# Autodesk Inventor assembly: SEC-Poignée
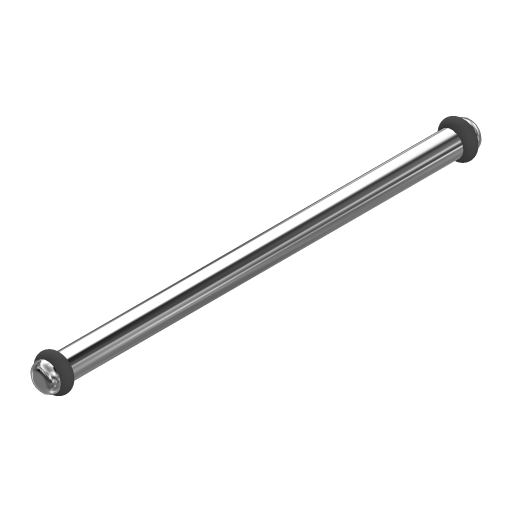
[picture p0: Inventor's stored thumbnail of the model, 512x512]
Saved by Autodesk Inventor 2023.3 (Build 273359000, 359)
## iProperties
Created: 2024-11
Part Number: SEC-Poignée
Document SubType Name: Assembly
Designer: Thier
Author: Thier
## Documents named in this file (3)
- E:\Etau dif Model\105 etau\EC02-TP05-Etau\EC02-TP05-02-Etau3D\SEC a refaire\SEC-Poignée.iam
- E:\Etau dif Model\105 etau\EC02-TP05-Etau\EC02-TP05-02-Etau3D\SEC a refaire\04-Poignee.ipt
- E:\Etau dif Model\105 etau\EC02-TP05-Etau\EC02-TP05-02-Etau3D\SEC a refaire\05-Butee de Poignee.ipt
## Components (3 placed, 2 different names)
1. 04-Poignee:1 — Logement:1, Logement:2
2. 05-Butee de Poignee:1 — Logement:2
3. 05-Butee de Poignee:2 — Logement:1
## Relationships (2: Insert 2)
- Logement:1 [Insert]: 04-Poignee:1 ↔ 05-Butee de Poignee:2
- Logement:2 [Insert]: 04-Poignee:1 ↔ 05-Butee de Poignee:1
